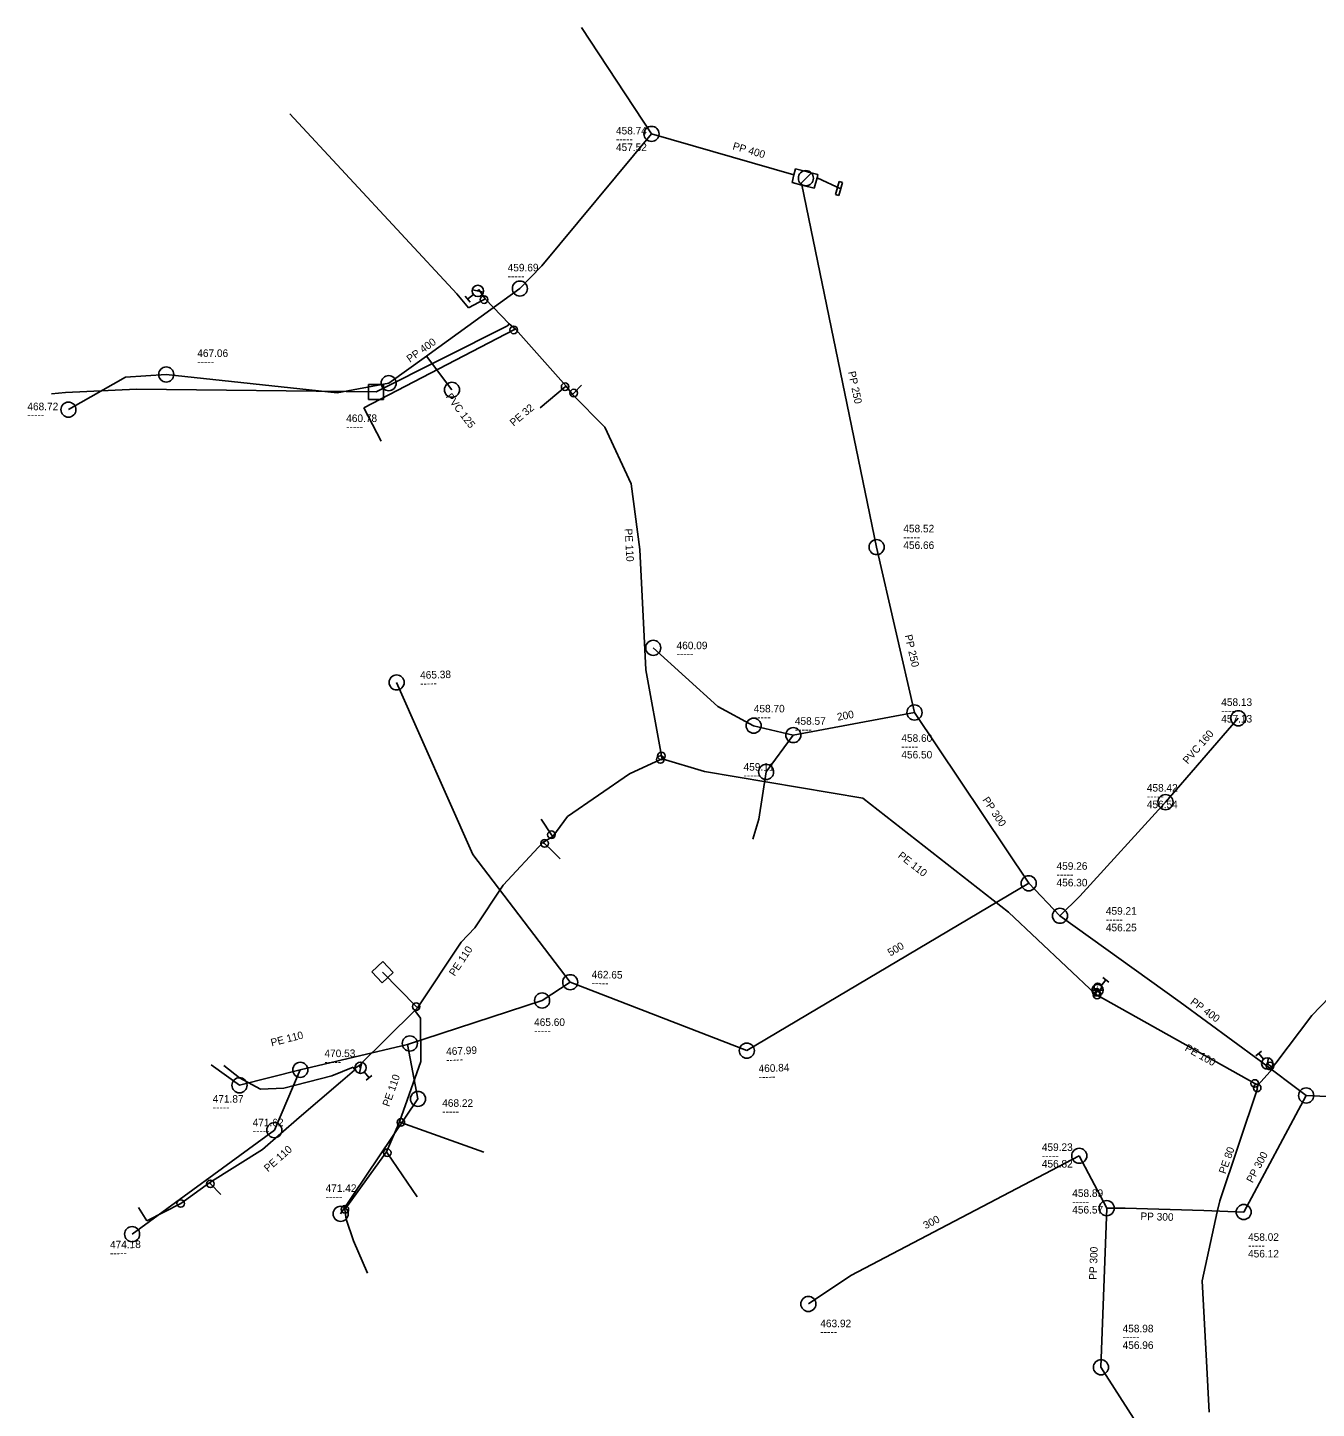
# Model space of a CAD drawing. Extents: x -685980 to -685723, y -1164236 to -1163951.
# Drawn here: x -685980 to -685809.2, y -1164133.5 to -1163950.6 of the extents above; entities that cross this region are included whole.
import ezdxf

# ---------------------------------------------------------------- set-up
doc = ezdxf.new("R2010")
doc.units = 0
doc.layers.add('Level 0', color=7, linetype='Continuous')

msp = doc.modelspace()

# ---------------------------------------------------------------- linework, layer by layer
at = {"layer": 'Level 0'}
for p, q in [((-685906.6, -1163950.58), (-685897.33, -1163964.66)), ((-685923.12, -1163985.83), (-685945.26, -1163962)), ((-685911.86, -1163982.13), (-685897.33, -1163964.66)), ((-685897.33, -1163964.66), (-685878.47, -1163970.1)), ((-685878.72, -1163971.1), (-685878.47, -1163970.1)), ((-685878.47, -1163970.1), (-685878.27, -1163969.29)), ((-685878.27, -1163969.29), (-685876.65, -1163969.7)), ((-685877.57, -1163971.25), (-685876.16, -1163969.85)), ((-685876.65, -1163969.7), (-685876.53, -1163969.73)), ((-685876.53, -1163969.73), (-685875.29, -1163970.05)), ((-685875.4, -1163970.47), (-685875.77, -1163971.87)), ((-685875.29, -1163970.05), (-685875.4, -1163970.47)), ((-685875.4, -1163970.47), (-685872.16, -1163971.98)), ((-685877.43, -1163971.44), (-685878.72, -1163971.1)), ((-685877.43, -1163971.43), (-685867.51, -1164019.4)), ((-685875.77, -1163971.87), (-685877.43, -1163971.44)), ((-685872.96, -1163972.68), (-685872.45, -1163970.97)), ((-685872.53, -1163972.81), (-685872.96, -1163972.68)), ((-685872.02, -1163971.1), (-685872.53, -1163972.81)), ((-685872.45, -1163970.97), (-685872.02, -1163971.1)), ((-685914.77, -1163985.15), (-685911.86, -1163982.13)), ((-685926.8, -1163993.85), (-685914.77, -1163985.15)), ((-685919.61, -1163985.62), (-685921.07, -1163985.3)), ((-685920.2, -1163985.28), (-685920.34, -1163985.46)), ((-685919.38, -1163986.53), (-685920.2, -1163985.28)), ((-685921.58, -1163987.7), (-685923.12, -1163985.83)), ((-685921.38, -1163986.96), (-685922.01, -1163986.18)), ((-685920.92, -1163985.94), (-685921.69, -1163986.57)), ((-685919.52, -1163986.61), (-685921.58, -1163987.7)), ((-685919.38, -1163986.53), (-685919.52, -1163986.61)), ((-685916.21, -1163989.82), (-685919.38, -1163986.53)), ((-685915.59, -1163990.63), (-685935.43, -1164000.94)), ((-685933.83, -1163998.84), (-685916.42, -1163990.07)), ((-685916.42, -1163990.07), (-685916.21, -1163989.82)), ((-685915.37, -1163990.51), (-685916.21, -1163989.82)), ((-685915.37, -1163990.51), (-685915.59, -1163990.63)), ((-685908.66, -1163998.07), (-685915.37, -1163990.51)), ((-685932.15, -1163997.68), (-685927.15, -1163994.1)), ((-685927.15, -1163994.1), (-685926.8, -1163993.85)), ((-685927.15, -1163994.1), (-685923.77, -1163998.56)), ((-685967.02, -1163996.91), (-685961.62, -1163996.53)), ((-685961.62, -1163996.53), (-685939, -1163998.98)), ((-685974.58, -1164001.19), (-685967.02, -1163996.91)), ((-685939, -1163998.98), (-685932.15, -1163997.68)), ((-685932.83, -1163997.84), (-685934.83, -1163997.84)), ((-685934.83, -1163997.84), (-685934.83, -1163999.84)), ((-685932.83, -1163999.84), (-685932.83, -1163997.84)), ((-685908.78, -1163998.16), (-685912.1, -1164000.96)), ((-685908.66, -1163998.07), (-685908.78, -1163998.16)), ((-685907.8, -1163999.18), (-685908.66, -1163998.07)), ((-685907.64, -1163998.99), (-685906.6, -1163997.96)), ((-685974.98, -1163998.94), (-685976.84, -1163999.11)), ((-685974.98, -1163998.94), (-685965.57, -1163998.46)), ((-685965.57, -1163998.46), (-685933.83, -1163998.84)), ((-685934.83, -1163999.84), (-685932.83, -1163999.84)), ((-685907.8, -1163999.18), (-685907.64, -1163998.99)), ((-685903.5, -1164003.51), (-685907.8, -1163999.18)), ((-685935.43, -1164000.94), (-685933.14, -1164005.37)), ((-685900.02, -1164011.02), (-685903.5, -1164003.51)), ((-685898.9, -1164019.71), (-685900.02, -1164011.02)), ((-685898.08, -1164035.64), (-685898.9, -1164019.71)), ((-685867.51, -1164019.4), (-685862.49, -1164041.32)), ((-685897.1, -1164032.75), (-685888.53, -1164040.5)), ((-685896.03, -1164047.07), (-685898.08, -1164035.64)), ((-685931.1, -1164037.33), (-685921, -1164060.12)), ((-685888.53, -1164040.5), (-685883.8, -1164043.06)), ((-685878.55, -1164044.31), (-685862.49, -1164041.32)), ((-685862.49, -1164041.32), (-685847.36, -1164063.94)), ((-685829.24, -1164053.19), (-685819.59, -1164042.08)), ((-685883.8, -1164043.06), (-685878.55, -1164044.31)), ((-685882.15, -1164049.19), (-685878.55, -1164044.31)), ((-685896.16, -1164047.54), (-685900.23, -1164049.46)), ((-685895.92, -1164047.44), (-685896.16, -1164047.54)), ((-685895.92, -1164047.44), (-685896.03, -1164047.07)), ((-685890.32, -1164049.14), (-685895.92, -1164047.44)), ((-685900.23, -1164049.46), (-685908.45, -1164055.08)), ((-685869.33, -1164052.67), (-685890.32, -1164049.14)), ((-685883.12, -1164055.43), (-685882.15, -1164049.19)), ((-685850.03, -1164067.77), (-685869.33, -1164052.67)), ((-685840.57, -1164065.65), (-685829.24, -1164053.19)), ((-685908.45, -1164055.08), (-685910.4, -1164057.73)), ((-685910.6, -1164057.5), (-685911.97, -1164055.43)), ((-685883.91, -1164058.09), (-685883.12, -1164055.43)), ((-685911.72, -1164058.55), (-685916.98, -1164064.21)), ((-685910.4, -1164057.73), (-685911.72, -1164058.55)), ((-685911.72, -1164058.55), (-685911.49, -1164058.66)), ((-685911.49, -1164058.66), (-685910.45, -1164059.69)), ((-685910.4, -1164057.73), (-685910.6, -1164057.5)), ((-685921, -1164060.12), (-685908.1, -1164077.05)), ((-685910.45, -1164059.69), (-685909.44, -1164060.7)), ((-685916.98, -1164064.21), (-685920.75, -1164069.83)), ((-685884.71, -1164086.11), (-685847.36, -1164063.94)), ((-685847.36, -1164063.94), (-685843.22, -1164068.24)), ((-685843.22, -1164068.24), (-685840.57, -1164065.65)), ((-685838.53, -1164078.61), (-685850.03, -1164067.77)), ((-685843.22, -1164068.24), (-685827.3, -1164079.7)), ((-685920.75, -1164069.83), (-685922.55, -1164071.72)), ((-685922.55, -1164071.72), (-685928.32, -1164080.42)), ((-685932.91, -1164074.3), (-685934.37, -1164075.66)), ((-685931.55, -1164075.76), (-685932.91, -1164074.3)), ((-685802.5, -1164073.83), (-685809.86, -1164081.45)), ((-685934.37, -1164075.66), (-685933.01, -1164077.12)), ((-685933.01, -1164077.12), (-685931.55, -1164075.76)), ((-685928.51, -1164080.28), (-685932.96, -1164075.71)), ((-685837.77, -1164077.51), (-685837.13, -1164076.74)), ((-685837.52, -1164076.42), (-685836.74, -1164077.05)), ((-685911.83, -1164079.47), (-685908.1, -1164077.05)), ((-685908.1, -1164077.05), (-685884.71, -1164086.11)), ((-685838.99, -1164078.08), (-685837.49, -1164078.11)), ((-685838.53, -1164078.61), (-685838.4, -1164078.37)), ((-685838.3, -1164078.76), (-685838.53, -1164078.61)), ((-685838.4, -1164078.37), (-685838.24, -1164078.09)), ((-685817.42, -1164090.46), (-685838.3, -1164078.76)), ((-685929.65, -1164085.31), (-685911.83, -1164079.47)), ((-685928.32, -1164080.42), (-685928.69, -1164080.78)), ((-685928.32, -1164080.42), (-685928.51, -1164080.28)), ((-685827.3, -1164079.7), (-685816.81, -1164087.37)), ((-685928.69, -1164080.78), (-685936.05, -1164088.07)), ((-685927.94, -1164081.83), (-685928.69, -1164080.78)), ((-685927.9, -1164087.56), (-685927.94, -1164081.83)), ((-685809.86, -1164081.45), (-685814.64, -1164087.76)), ((-685943.86, -1164088.66), (-685929.65, -1164085.31)), ((-685928.27, -1164092.51), (-685929.65, -1164085.31)), ((-685817.27, -1164086.8), (-685816.5, -1164086.16)), ((-685955.68, -1164088), (-685951.92, -1164090.7)), ((-685935.73, -1164087.64), (-685936.03, -1164089.11)), ((-685930.71, -1164095.55), (-685927.9, -1164087.56)), ((-685816.24, -1164087.25), (-685816.88, -1164086.48)), ((-685816.81, -1164087.37), (-685810.6, -1164092.06)), ((-685815.91, -1164088.55), (-685815.6, -1164087.08)), ((-685815.76, -1164087.82), (-685815.38, -1164088.14)), ((-685815.12, -1164088.35), (-685814.64, -1164087.76)), ((-685951.91, -1164089.73), (-685953.99, -1164088.06)), ((-685951.92, -1164090.7), (-685943.86, -1164088.66)), ((-685949.15, -1164091.22), (-685951.91, -1164089.73)), ((-685947.3, -1164096.65), (-685943.86, -1164088.66)), ((-685939.69, -1164089.46), (-685946.03, -1164091.07)), ((-685936.84, -1164088.29), (-685939.69, -1164089.46)), ((-685936.68, -1164088.71), (-685938.53, -1164090.27)), ((-685936.74, -1164088.53), (-685936.84, -1164088.29)), ((-685936.05, -1164088.07), (-685936.74, -1164088.53)), ((-685936.74, -1164088.53), (-685936.68, -1164088.71)), ((-685936.05, -1164088.07), (-685935.88, -1164088.37)), ((-685935.4, -1164088.94), (-685934.75, -1164089.71)), ((-685934.37, -1164089.39), (-685935.14, -1164090.03)), ((-685815.41, -1164088.94), (-685816.96, -1164090.64)), ((-685814.99, -1164088.47), (-685815.41, -1164088.94)), ((-685815.38, -1164088.14), (-685815.12, -1164088.35)), ((-685815.12, -1164088.35), (-685814.99, -1164088.47)), ((-685946.03, -1164091.07), (-685949.15, -1164091.22)), ((-685938.53, -1164090.27), (-685944.03, -1164094.96)), ((-685817.06, -1164091.12), (-685822.02, -1164105.99)), ((-685816.96, -1164090.64), (-685817.42, -1164090.46)), ((-685817.09, -1164091.05), (-685817.1, -1164091.11)), ((-685817.1, -1164091.11), (-685817.06, -1164091.12)), ((-685816.96, -1164090.64), (-685817.09, -1164091.05)), ((-685938.52, -1164107.73), (-685928.27, -1164092.51)), ((-685818.88, -1164107.49), (-685810.6, -1164092.06)), ((-685810.6, -1164092.06), (-685791.4, -1164093.03)), ((-685944.03, -1164094.96), (-685948.86, -1164099.23)), ((-685966.15, -1164110.42), (-685947.3, -1164096.65)), ((-685932.46, -1164099.51), (-685930.71, -1164095.55)), ((-685930.71, -1164095.55), (-685930.54, -1164095.62)), ((-685930.54, -1164095.62), (-685919.54, -1164099.54)), ((-685948.86, -1164099.23), (-685955.84, -1164103.59)), ((-685937.96, -1164107.14), (-685932.46, -1164099.51)), ((-685932.46, -1164099.51), (-685932.34, -1164099.63)), ((-685932.34, -1164099.63), (-685928.38, -1164105.46)), ((-685870.94, -1164115.9), (-685840.66, -1164100.04)), ((-685840.66, -1164100.04), (-685837.03, -1164106.98)), ((-685955.84, -1164103.59), (-685959.7, -1164106.36)), ((-685955.84, -1164103.59), (-685955.77, -1164103.76)), ((-685955.77, -1164103.76), (-685954.37, -1164105.16)), ((-685822.02, -1164105.99), (-685822.38, -1164107.45)), ((-685964.19, -1164108.66), (-685965.32, -1164106.89)), ((-685959.7, -1164106.36), (-685964.19, -1164108.66)), ((-685937.79, -1164108.42), (-685937.96, -1164107.14)), ((-685837.79, -1164128.06), (-685837.03, -1164106.98)), ((-685837.03, -1164106.98), (-685834.57, -1164106.98)), ((-685834.57, -1164106.98), (-685824.16, -1164107.28)), ((-685822.38, -1164107.45), (-685824.37, -1164116.6)), ((-685824.16, -1164107.28), (-685818.88, -1164107.49)), ((-685936.82, -1164111.29), (-685937.79, -1164108.42)), ((-685934.94, -1164115.61), (-685936.82, -1164111.29)), ((-685876.55, -1164119.67), (-685870.94, -1164115.9)), ((-685824.37, -1164116.6), (-685823.79, -1164127.25)), ((-685831.31, -1164138.15), (-685837.79, -1164128.06)), ((-685823.79, -1164127.25), (-685823.46, -1164134))]:
    msp.add_line(p, q, dxfattribs=at)
for centre, radius in [((-685897.33, -1163964.66), 1), ((-685876.88, -1163970.53), 1), ((-685920.34, -1163985.46), 0.75), ((-685914.77, -1163985.15), 1), ((-685919.52, -1163986.61), 0.5), ((-685915.59, -1163990.63), 0.5), ((-685961.62, -1163996.53), 1), ((-685932.15, -1163997.68), 1), ((-685923.77, -1163998.56), 1), ((-685908.78, -1163998.16), 0.5), ((-685974.58, -1164001.19), 1), ((-685907.64, -1163998.99), 0.5), ((-685867.51, -1164019.4), 1), ((-685897.1, -1164032.75), 1), ((-685931.1, -1164037.33), 1), ((-685862.49, -1164041.32), 1), ((-685883.8, -1164043.06), 1), ((-685819.59, -1164042.08), 1), ((-685878.55, -1164044.31), 1), ((-685896.16, -1164047.54), 0.5), ((-685896.03, -1164047.07), 0.5), ((-685882.15, -1164049.19), 1), ((-685829.24, -1164053.19), 1), ((-685911.49, -1164058.66), 0.5), ((-685910.6, -1164057.5), 0.5), ((-685847.36, -1164063.94), 1), ((-685843.22, -1164068.24), 1), ((-685908.1, -1164077.05), 1), ((-685911.83, -1164079.47), 1), ((-685838.24, -1164078.09), 0.75), ((-685838.4, -1164078.37), 0.5), ((-685838.3, -1164078.76), 0.5), ((-685838.21, -1164077.67), 0.5), ((-685838.21, -1164077.67), 0.001), ((-685928.51, -1164080.28), 0.5), ((-685929.35, -1164085.16), 1), ((-685884.71, -1164086.11), 1), ((-685943.86, -1164088.66), 1), ((-685935.88, -1164088.37), 0.75), ((-685815.76, -1164087.82), 0.75), ((-685815.38, -1164088.14), 0.5), ((-685951.92, -1164090.7), 1), ((-685928.27, -1164092.51), 1), ((-685817.42, -1164090.46), 0.5), ((-685817.09, -1164091.05), 0.5), ((-685810.6, -1164092.06), 1), ((-685930.54, -1164095.62), 0.5), ((-685947.3, -1164096.65), 1), ((-685932.34, -1164099.63), 0.5), ((-685840.66, -1164100.04), 1), ((-685955.77, -1164103.76), 0.5), ((-685959.7, -1164106.36), 0.5), ((-685837.03, -1164106.98), 1), ((-685938.52, -1164107.73), 1), ((-685937.96, -1164107.14), 0.5), ((-685818.88, -1164107.49), 1), ((-685966.15, -1164110.42), 1), ((-685876.55, -1164119.67), 1), ((-685837.79, -1164128.06), 1)]:
    msp.add_circle(centre, radius, dxfattribs=at)

# ---------------------------------------------------------------- texts
for s, p in [('458.74', (-685902.04, -1163964.73)), ('-----', (-685902.04, -1163965.83)), ('457.52', (-685902.04, -1163966.93)), ('467.06', (-685957.51, -1163994.21)), ('-----', (-685957.51, -1163995.31)), ('468.72', (-685980.02, -1164001.27)), ('-----', (-685980.02, -1164002.37)), ('460.78', (-685937.78, -1164002.83)), ('-----', (-685937.78, -1164003.93)), ('458.52', (-685863.97, -1164017.45)), ('-----', (-685863.97, -1164018.55)), ('456.66', (-685863.97, -1164019.65)), ('460.09', (-685894.01, -1164032.93)), ('-----', (-685894.01, -1164034.03)), ('458.70', (-685883.78, -1164041.3)), ('458.13', (-685821.85, -1164040.44)), ('-----', (-685883.78, -1164042.4)), ('458.57', (-685878.34, -1164042.94)), ('457.13', (-685821.85, -1164042.64)), ('-----', (-685821.85, -1164041.54)), ('-----', (-685878.34, -1164044.04)), ('458.60', (-685864.23, -1164045.2)), ('-----', (-685864.23, -1164046.3)), ('456.50', (-685864.23, -1164047.4)), ('459.11', (-685885.14, -1164049.02)), ('-----', (-685885.14, -1164050.12)), ('458.42', (-685831.71, -1164051.79)), ('456.54', (-685831.71, -1164053.99)), ('-----', (-685831.71, -1164052.89)), ('459.26', (-685843.67, -1164062.15)), ('456.30', (-685843.67, -1164064.35)), ('-----', (-685843.67, -1164063.25)), ('459.21', (-685837.14, -1164068.1)), ('456.25', (-685837.14, -1164070.3)), ('-----', (-685837.14, -1164069.2)), ('465.60', (-685912.89, -1164082.84)), ('-----', (-685912.89, -1164083.94)), ('471.62', (-685950.17, -1164096.13)), ('-----', (-685950.17, -1164097.23)), ('459.23', (-685845.62, -1164099.4)), ('456.82', (-685845.62, -1164101.6)), ('-----', (-685845.62, -1164100.5)), ('458.89', (-685841.59, -1164105.49)), ('-----', (-685841.59, -1164106.59)), ('456.57', (-685841.59, -1164107.69)), ('458.02', (-685818.3, -1164111.31)), ('456.12', (-685818.3, -1164113.51)), ('-----', (-685818.3, -1164112.41)), ('463.92', (-685874.97, -1164122.75)), ('458.98', (-685834.92, -1164123.43)), ('-----', (-685874.97, -1164123.85)), ('-----', (-685834.92, -1164124.53)), ('456.96', (-685834.92, -1164125.63))]:
    msp.add_text(s, height=1, dxfattribs=at).set_placement(p)
for s, rotation, p in [('PP 400', 343.899, (-685886.66, -1163966.69)), ('459.69', 0.223, (-685916.39, -1163982.88)), ('-----', 0.223, (-685916.39, -1163983.98)), ('PP 400', 35.598, (-685929.34, -1163994.99)), ('PP 250', 281.691, (-685871.29, -1163996.2)), ('PVC 125', 307.157, (-685924.63, -1163999.49)), ('PE 32', 40.154, (-685915.59, -1164003.46)), ('PE 110', 272.947, (-685900.88, -1164016.97)), ('PP 250', 282.906, (-685863.8, -1164031.11)), ('465.38', 1.587, (-685927.98, -1164036.86)), ('-----', 1.587, (-685927.98, -1164037.96)), ('200', 10.558, (-685872.65, -1164042.41)), ('PVC 160', 49.023, (-685826.29, -1164048.22)), ('PP 300', 303.764, (-685853.54, -1164052.9)), ('PE 110', 321.961, (-685864.77, -1164060.44)), ('PE 110', 56.447, (-685923.41, -1164076.33)), ('500', 30.695, (-685865.69, -1164073.65)), ('462.65', 359.272, (-685905.27, -1164076.52)), ('-----', 359.272, (-685905.27, -1164077.62)), ('PP 400', 323.825, (-685826.04, -1164079.84)), ('PE 110', 14.249, (-685947.64, -1164085.56)), ('470.53', 0.302, (-685940.66, -1164086.98)), ('467.99', 2.667, (-685924.52, -1164086.72)), ('PE 100', 330.736, (-685826.77, -1164086.06)), ('-----', 0.302, (-685940.66, -1164088.08)), ('-----', 2.667, (-685924.52, -1164087.82)), ('460.84', 2.346, (-685883.13, -1164088.99)), ('PE 110', 70.624, (-685932.08, -1164093.61)), ('-----', 2.346, (-685883.13, -1164090.09)), ('471.87', 359.705, (-685955.47, -1164092.99)), ('468.22', 359.869, (-685925.06, -1164093.55)), ('-----', 359.705, (-685955.47, -1164094.09)), ('-----', 359.869, (-685925.06, -1164094.65)), ('PE 110', 41.479, (-685948.14, -1164102.24)), ('PE 80', 70.617, (-685821.28, -1164102.52)), ('PP 300', 61.784, (-685817.71, -1164103.71)), ('471.42', 0.152, (-685940.51, -1164104.84)), ('-----', 0.152, (-685940.51, -1164105.94)), ('300', 27.635, (-685861.02, -1164109.79)), ('PP 300', 358.327, (-685832.57, -1164108.54)), ('474.18', 0.767, (-685969.07, -1164112.32)), ('-----', 0.767, (-685969.07, -1164113.42)), ('PP 300', 87.94, (-685838.37, -1164116.49))]:
    msp.add_text(s, height=1, rotation=rotation, dxfattribs=at).set_placement(p)

doc.saveas('drawing.dxf')
